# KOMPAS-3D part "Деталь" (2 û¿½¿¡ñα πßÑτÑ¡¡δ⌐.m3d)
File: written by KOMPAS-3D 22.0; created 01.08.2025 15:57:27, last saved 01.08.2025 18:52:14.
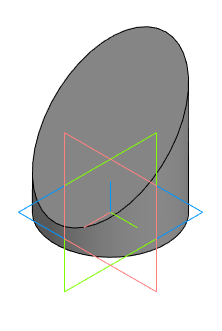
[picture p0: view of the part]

Document properties: Автор: user; Полное имя файла: G:\08 01 пятница\2025 НГ Лаб работы\Лаб 2 Сечение цилиндра\Цилиндр усеченный.m3d

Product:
- Part/product: Деталь
    Масса: 0.888593

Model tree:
1. Эскиз:1
2. Элемент выдавливания:1
     Расстояние 1 = 70
3. Эскиз:2  (with: Элемент выдавливания:1)
4. Элемент выдавливания:2
     Расстояние 1 = 30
